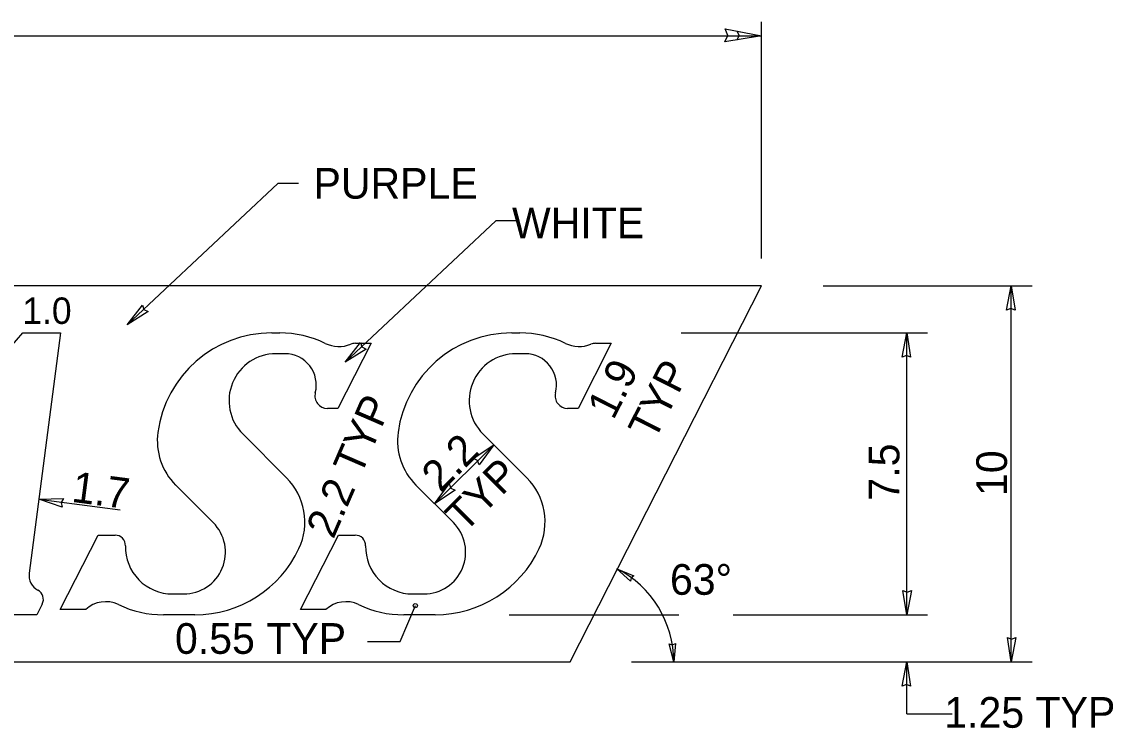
# Model space of a CAD drawing. Extents: x 10268197 to 10269179, y 2141503 to 2142677.
# Drawn here: x 10268496.32 to 10268521.21, y 2142049.29 to 2142065.4 of the extents above; entities that cross this region are included whole.
import ezdxf

# ---------------------------------------------------------------- set-up
doc = ezdxf.new("R2010")
doc.units = 0
for name, color, linetype in [('1', 7, 'Continuous'), ('2', 7, 'Continuous'), ('52', 7, 'Continuous')]:
    doc.layers.add(name, color=color, linetype=linetype)

msp = doc.modelspace()

# ---------------------------------------------------------------- linework, layer by layer
at = {"layer": '1'}
for p, q in [((10268513.188, 2142060.006), (10268513.188, 2142065.401)), ((10268471.492, 2142065.08), (10268513.188, 2142065.08)), ((10268514.594, 2142059.378), (10268519.359, 2142059.378)), ((10268518.882, 2142050.803), (10268518.882, 2142059.378)), ((10268511.353, 2142058.307), (10268516.976, 2142058.307)), ((10268516.5, 2142051.875), (10268516.5, 2142058.307)), ((10268505.732, 2142054.407), (10268507.08, 2142055.753)), ((10268496.703, 2142054.511), (10268498.561, 2142054.269)), ((10268504.942, 2142051.268), (10268505.292, 2142052.085)), ((10268507.435, 2142051.875), (10268511.298, 2142051.875)), ((10268512.542, 2142051.875), (10268516.976, 2142051.875)), ((10268504.202, 2142051.268), (10268504.942, 2142051.268)), ((10268510.225, 2142050.803), (10268519.359, 2142050.803)), ((10268516.5, 2142049.614), (10268516.5, 2142050.803)), ((10268516.5, 2142049.614), (10268517.537, 2142049.614))]:
    msp.add_line(p, q, dxfattribs=at)
for points in [[(10268502.63, 2142061.712), (10268502.152, 2142061.712), (10268498.721, 2142058.49)], [(10268507.603, 2142060.86), (10268507.125, 2142060.86), (10268503.693, 2142057.638)]]:
    msp.add_lwpolyline(points, dxfattribs=at)
msp.add_circle((10268505.291, 2142052.085), 0.0476, dxfattribs=at)
msp.add_arc((10268508.804, 2142050.804), 2.382, 0, 63.0012, dxfattribs=at)
at = {"layer": '2'}
for p, q in [((10268513.188, 2142059.378), (10268487.339, 2142059.378)), ((10268508.819, 2142050.803), (10268513.188, 2142059.378)), ((10268491.475, 2142052.711), (10268496.34, 2142058.307)), ((10268496.34, 2142058.307), (10268497.197, 2142058.307)), ((10268497.197, 2142058.307), (10268496.483, 2142052.825)), ((10268502.016, 2142058.307), (10268502.197, 2142058.307)), ((10268507.494, 2142058.307), (10268507.675, 2142058.307)), ((10268504.282, 2142058.068), (10268503.525, 2142056.583)), ((10268503.926, 2142058.068), (10268504.282, 2142058.068)), ((10268509.761, 2142058.068), (10268509.004, 2142056.583)), ((10268509.403, 2142058.068), (10268509.761, 2142058.068)), ((10268502.316, 2142057.83), (10268502.114, 2142057.83)), ((10268507.796, 2142057.83), (10268507.591, 2142057.83)), ((10268503.525, 2142056.583), (10268503.286, 2142056.583)), ((10268509.004, 2142056.583), (10268508.765, 2142056.583)), ((10268501.355, 2142056), (10268502.353, 2142055.002)), ((10268506.833, 2142056), (10268507.832, 2142055.002)), ((10268500.682, 2142053.978), (10268499.825, 2142054.834)), ((10268506.16, 2142053.978), (10268505.303, 2142054.834)), ((10268497.194, 2142051.995), (10268498.059, 2142053.691)), ((10268498.059, 2142053.691), (10268498.441, 2142053.691)), ((10268502.672, 2142051.995), (10268503.537, 2142053.691)), ((10268503.537, 2142053.691), (10268503.92, 2142053.691)), ((10268499.75, 2142052.351), (10268500.007, 2142052.351)), ((10268505.231, 2142052.351), (10268505.487, 2142052.351)), ((10268496.782, 2142052.12), (10268496.656, 2142051.874)), ((10268497.773, 2142051.995), (10268497.194, 2142051.995)), ((10268503.251, 2142051.995), (10268502.672, 2142051.995)), ((10268496.656, 2142051.874), (10268494.274, 2142051.874)), ((10268500.264, 2142051.874), (10268499.548, 2142051.874)), ((10268505.742, 2142051.874), (10268505.026, 2142051.874)), ((10268486.553, 2142050.803), (10268508.819, 2142050.803))]:
    msp.add_line(p, q, dxfattribs=at)
for centre, radius, start, end in [((10268502.015, 2142055.686), 2.62, 90, 172.3089), ((10268502.196, 2142055.924), 2.382, 64.0896, 90), ((10268507.494, 2142055.686), 2.62, 90, 172.3089), ((10268507.675, 2142055.924), 2.382, 64.0896, 90), ((10268503.549, 2142058.71), 0.715, 244.0896, 292.0347), ((10268503.924, 2142057.782), 0.286, 90, 112.0347), ((10268509.028, 2142058.71), 0.715, 244.0896, 292.0347), ((10268509.403, 2142057.782), 0.286, 90, 112.0347), ((10268502.113, 2142056.758), 1.072, 90, 225), ((10268502.317, 2142057.115), 0.715, 345.6915, 90), ((10268507.591, 2142056.758), 1.072, 90, 225), ((10268507.796, 2142057.115), 0.715, 345.6915, 90), ((10268503.287, 2142056.868), 0.286, 165.6915, 270), ((10268508.765, 2142056.868), 0.286, 165.6915, 270), ((10268500.835, 2142055.846), 1.429, 172.3089, 225), ((10268506.314, 2142055.846), 1.429, 172.3089, 225), ((10268501.343, 2142053.991), 1.429, 334.95, 45), ((10268506.821, 2142053.991), 1.429, 334.95, 45), ((10268500.008, 2142053.304), 0.953, 270, 45), ((10268505.486, 2142053.304), 0.953, 270, 45), ((10268498.441, 2142053.454), 0.238, 358.6664, 90), ((10268503.92, 2142053.454), 0.238, 358.6664, 90), ((10268499.751, 2142053.423), 1.072, 178.6665, 270), ((10268505.23, 2142053.423), 1.072, 178.6665, 270), ((10268500.264, 2142054.495), 2.62, 270, 334.95), ((10268505.742, 2142054.495), 2.62, 270, 334.95), ((10268496.861, 2142052.775), 0.381, 172.5884, 241.8673), ((10268496.569, 2142052.229), 0.238, 332.9784, 61.8673), ((10268498.229, 2142051.508), 0.667, 64.3795, 133.1892), ((10268503.707, 2142051.508), 0.667, 64.3795, 133.1892), ((10268499.547, 2142054.257), 2.382, 244.3795, 270), ((10268505.026, 2142054.257), 2.382, 244.3795, 270)]:
    msp.add_arc(centre, radius, start, end, dxfattribs=at)
at = {"layer": '52'}
for points in [[(10268513.188, 2142065.08), (10268512.353, 2142064.948), (10268512.416, 2142065.091), (10268512.359, 2142065.24)], [(10268513.188, 2142065.08), (10268512.632, 2142064.992), (10268512.674, 2142065.087), (10268512.635, 2142065.187)], [(10268518.882, 2142059.378), (10268518.969, 2142058.822), (10268518.874, 2142058.864), (10268518.775, 2142058.826)], [(10268498.721, 2142058.49), (10268499.066, 2142058.935), (10268499.101, 2142058.836), (10268499.197, 2142058.79)], [(10268516.5, 2142058.307), (10268516.588, 2142057.75), (10268516.492, 2142057.792), (10268516.393, 2142057.754)], [(10268503.693, 2142057.638), (10268504.039, 2142058.083), (10268504.074, 2142057.984), (10268504.169, 2142057.938)], [(10268507.08, 2142055.753), (10268506.748, 2142055.298), (10268506.711, 2142055.395), (10268506.614, 2142055.438)], [(10268505.732, 2142054.407), (10268506.064, 2142054.862), (10268506.102, 2142054.765), (10268506.199, 2142054.722)], [(10268496.703, 2142054.511), (10268497.266, 2142054.526), (10268497.212, 2142054.437), (10268497.237, 2142054.333)], [(10268509.885, 2142052.926), (10268510.276, 2142052.765), (10268510.212, 2142052.72), (10268510.198, 2142052.643)], [(10268516.5, 2142051.875), (10268516.412, 2142052.432), (10268516.508, 2142052.39), (10268516.607, 2142052.428)], [(10268511.186, 2142050.803), (10268511.08, 2142051.213), (10268511.155, 2142051.188), (10268511.226, 2142051.223)], [(10268518.882, 2142050.803), (10268518.794, 2142051.36), (10268518.89, 2142051.318), (10268518.989, 2142051.356)], [(10268516.5, 2142050.803), (10268516.588, 2142050.247), (10268516.492, 2142050.289), (10268516.393, 2142050.251)]]:
    msp.add_lwpolyline(points, close=True, dxfattribs=at)

# ---------------------------------------------------------------- texts
at = {"layer": '1'}
for s, height, p in [('PURPLE', 0.7, (10268502.968, 2142061.367)), ('WHITE', 0.7, (10268507.496, 2142060.465)), ('1.0', 0.6037, (10268496.329, 2142058.51)), ('63°', 0.7, (10268511.099, 2142052.332)), ('0.55 TYP', 0.7, (10268499.809, 2142050.985)), ('1.25 TYP', 0.7, (10268517.355, 2142049.299))]:
    msp.add_text(s, height=height, dxfattribs=at).set_placement(p)
for s, rotation, p in [('1.9', 63, (10268509.808, 2142056.3)), ('TYP', 63, (10268510.744, 2142055.823)), ('2.2 TYP', 66.578, (10268503.421, 2142053.583)), ('2.2', 45, (10268505.866, 2142054.65)), ('7.5', 90, (10268516.332, 2142054.48)), ('10', 90, (10268518.786, 2142054.585)), ('TYP', 45, (10268506.412, 2142053.725)), ('1.7', 352.5994, (10268497.432, 2142054.454))]:
    msp.add_text(s, height=0.7, rotation=rotation, dxfattribs=at).set_placement(p)

doc.saveas('drawing.dxf')
